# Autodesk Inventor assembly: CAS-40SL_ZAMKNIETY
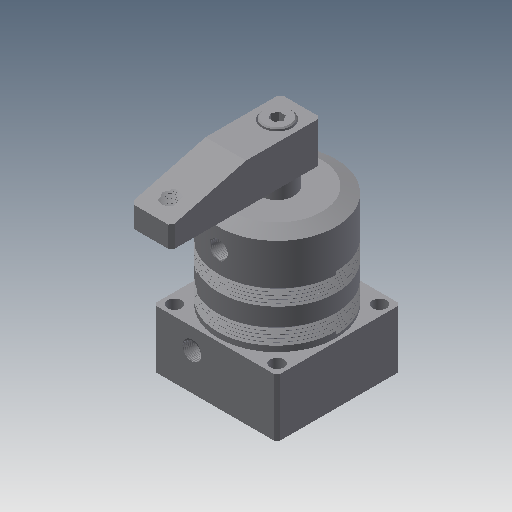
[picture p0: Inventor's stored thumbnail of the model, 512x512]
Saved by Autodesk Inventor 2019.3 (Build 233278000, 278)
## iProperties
Created: 2009-09
Part Number: CAS-40SL_ZAMKNIETY
Material: Ogólny
Document SubType Name: Assembly
Designer: CADENGINEERING4
Sending System: PRO/ENGINEER BY PARAMETRIC TECHNOLOGY CORPORATION, 2007170
Preprocessor: PRO/ENGINEER BY PARAMETRIC TECHNOLOGY CORPORATION, 2007170
Title: CAS-40S_ASM
Author: Administrator
Revision Number: 2LAST_VERSION
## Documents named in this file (7)
- D:\Vault_2016\Projekty\STRONA\Pneumatic\Line ; Pipe connecct - type\cas-40s_asm\CAS-40SL_ZAMKNIETY.iam
- D:\Vault_2016\Projekty\STRONA\Pneumatic\Line ; Pipe connecct - type\cas-40s_asm\CAS-40BT.ipt
- D:\Vault_2016\Projekty\STRONA\Pneumatic\Line ; Pipe connecct - type\cas-40s_asm\CAS-40HSG.ipt
- D:\Vault_2016\Projekty\STRONA\Pneumatic\Line ; Pipe connecct - type\cas-40s_asm\CAS-40HG.ipt
- D:\Vault_2016\Projekty\STRONA\Pneumatic\Line ; Pipe connecct - type\cas-40s_asm\M4.ipt
- D:\Vault_2016\Projekty\STRONA\Pneumatic\Line ; Pipe connecct - type\cas-40s_asm\CAS-32SYB.ipt
- D:\Vault_2016\Projekty\STRONA\Pneumatic\Line ; Pipe connecct - type\cas-40s_asm\M8LC.ipt
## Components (9 placed, 9 different names)
1. CAS-40BT_0 — Zestawiające:5, Kątowe:1, Równoległe:1
2. CAS-40HSG_1 — Zestawiające:1, Zestawiające:2, Zestawiające:4, Zestawiające:5
3. CAS-40HG_2
4. M4_3
5. M4_4
6. M4_5
7. M4_6
8. CAS-32SYB_7 — Zestawiające:1, Zestawiające:3, Zestawiające:4, Kątowe:1, Równoległe:1
9. M8LC_8 — Zestawiające:2, Zestawiające:3
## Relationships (7: Mate 5, Angle 1, Flush 1)
- Zestawiające:1 [Mate]: CAS-40HSG_1 ↔ CAS-32SYB_7
- Zestawiające:2 [Mate]: CAS-40HSG_1 ↔ M8LC_8
- Zestawiające:3 [Mate]: CAS-32SYB_7 ↔ M8LC_8
- Zestawiające:4 [Mate]: CAS-40HSG_1 ↔ CAS-32SYB_7
- Zestawiające:5 [Mate]: CAS-40BT_0 ↔ CAS-40HSG_1
- Kątowe:1 [Angle]: CAS-40BT_0 ↔ CAS-32SYB_7
- Równoległe:1 [Flush]: CAS-40BT_0 ↔ CAS-32SYB_7
